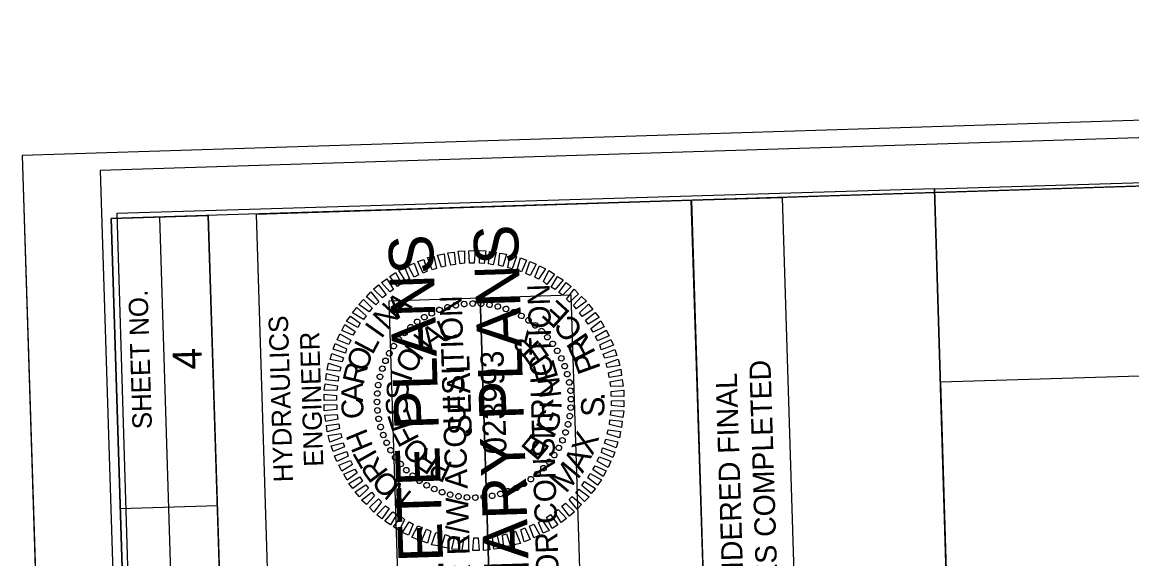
# Model space of a CAD drawing. Extents: x 2326025 to 2327173, y 123144 to 125024.
# Drawn here: x 2326025.5 to 2326312.3, y 124884.9 to 125023.6 of the extents above; entities that cross this region are included whole.
import ezdxf

# ---------------------------------------------------------------- set-up
doc = ezdxf.new("R2010")
doc.units = 0
for name, color, linetype in [('Sheet Clip Boundary CELL', 7, 'Continuous'), ('Sheet Cutting Line CELL', 7, 'Continuous'), ('Sheet Data Field CELL', 7, 'Continuous'), ('Sheet Layout Plan Border', 7, 'Continuous'), ('Sheet PE Seal Cell', 7, 'Continuous'), ('Sheet Plan CELL', 7, 'Continuous'), ('Sheet Plan Layout CELL', 7, 'Continuous'), ('Sheet Plot Border Inside CELL', 7, 'Continuous'), ('Sheet Plot Border Outside CELL', 7, 'Continuous'), ('Sheet Sticker Exception Certification CELL', 7, 'Continuous'), ('Sheet Sticker Incomplete CELL', 7, 'Continuous'), ('Sheet Sticker Preliminary CELL', 7, 'Continuous'), ('Typical Detail Wedge2 CELL', 7, 'Continuous')]:
    doc.layers.add(name, color=color, linetype=linetype)

msp = doc.modelspace()

# ---------------------------------------------------------------- linework, layer by layer
at = {"layer": 'Sheet Clip Boundary CELL'}
msp.add_lwpolyline([(2327143.22, 123556.44), (2327101.01, 124955.82), (2326262.87, 124930.53), (2326268.58, 124741.36), (2326057.19, 124734.98), (2326093.7, 123524.78)], close=True, dxfattribs=at)
at = {"layer": 'Sheet Cutting Line CELL'}
msp.add_line((2326025.47, 124989.14), (2326078.49, 123306.48), dxfattribs=at)
at = {"layer": 'Sheet Layout Plan Border'}
msp.add_lwpolyline([(2327143.22, 123556.44), (2327101.01, 124955.82), (2326262.87, 124930.53), (2326268.58, 124741.36), (2326057.19, 124734.98), (2326093.7, 123524.78)], close=True, dxfattribs=at)
at = {"layer": 'Sheet PE Seal Cell'}
for p, q in [((2326133.33, 124949.29), (2326133.33, 124949.29)), ((2326135.41, 124949.95), (2326135.41, 124949.95)), ((2326137.6, 124950.42), (2326137.6, 124950.42)), ((2326139.73, 124950.79), (2326139.73, 124950.79)), ((2326141.93, 124950.91), (2326141.93, 124950.91)), ((2326144.14, 124950.83), (2326144.14, 124950.83)), ((2326146.3, 124950.54), (2326146.3, 124950.54)), ((2326148.41, 124950.16), (2326148.41, 124950.16)), ((2326150.53, 124949.53), (2326150.53, 124949.53)), ((2326127.57, 124946.15), (2326127.57, 124946.15)), ((2326129.44, 124947.36), (2326129.44, 124947.36)), ((2326131.36, 124948.42), (2326131.36, 124948.42)), ((2326152.56, 124948.69), (2326152.56, 124948.69)), ((2326154.54, 124947.75), (2326154.54, 124947.75)), ((2326156.38, 124946.56), (2326156.38, 124946.56)), ((2326124.26, 124943.3), (2326124.26, 124943.3)), ((2326125.86, 124944.85), (2326125.86, 124944.85)), ((2326158.17, 124945.27), (2326158.17, 124945.27)), ((2326159.76, 124943.82), (2326159.76, 124943.82)), ((2326122.81, 124941.7), (2326122.81, 124941.7)), ((2326161.32, 124942.21), (2326161.32, 124942.21)), ((2326162.62, 124940.5), (2326162.62, 124940.5)), ((2326120.33, 124938.07), (2326120.33, 124938.07)), ((2326121.52, 124939.91), (2326121.52, 124939.91)), ((2326163.83, 124938.64), (2326163.83, 124938.64)), ((2326119.39, 124936.09), (2326119.39, 124936.09)), ((2326164.89, 124936.72), (2326164.89, 124936.72)), ((2326165.75, 124934.75), (2326165.75, 124934.75)), ((2326117.92, 124931.94), (2326117.92, 124931.94)), ((2326118.55, 124934.06), (2326118.55, 124934.06)), ((2326166.42, 124932.67), (2326166.42, 124932.67)), ((2326117.53, 124929.83), (2326117.53, 124929.83)), ((2326166.89, 124930.48), (2326166.89, 124930.48)), ((2326117.25, 124927.67), (2326117.25, 124927.67)), ((2326142.27, 124925.81), (2326142.27, 124925.81)), ((2326167.26, 124928.34), (2326167.26, 124928.34)), ((2326167.37, 124926.15), (2326167.37, 124926.15)), ((2326117.17, 124925.46), (2326117.17, 124925.46)), ((2326117.29, 124923.27), (2326117.29, 124923.27)), ((2326167.29, 124923.94), (2326167.29, 124923.94)), ((2326117.66, 124921.13), (2326117.66, 124921.13)), ((2326167.01, 124921.78), (2326167.01, 124921.78)), ((2326118.13, 124918.94), (2326118.13, 124918.94)), ((2326165.99, 124917.55), (2326165.99, 124917.55)), ((2326166.63, 124919.67), (2326166.63, 124919.67)), ((2326118.79, 124916.86), (2326118.79, 124916.86)), ((2326119.66, 124914.89), (2326119.66, 124914.89)), ((2326165.16, 124915.52), (2326165.16, 124915.52)), ((2326120.72, 124912.97), (2326120.72, 124912.97)), ((2326163.03, 124911.7), (2326163.03, 124911.7)), ((2326164.22, 124913.54), (2326164.22, 124913.54)), ((2326121.93, 124911.11), (2326121.93, 124911.11)), ((2326123.23, 124909.4), (2326123.23, 124909.4)), ((2326161.73, 124909.91), (2326161.73, 124909.91)), ((2326124.78, 124907.8), (2326124.78, 124907.8)), ((2326126.38, 124906.35), (2326126.38, 124906.35)), ((2326158.68, 124906.76), (2326158.68, 124906.76)), ((2326160.28, 124908.31), (2326160.28, 124908.31)), ((2326128.17, 124905.05), (2326128.17, 124905.05)), ((2326130.01, 124903.86), (2326130.01, 124903.86)), ((2326131.99, 124902.92), (2326131.99, 124902.92)), ((2326153.19, 124903.19), (2326153.19, 124903.19)), ((2326155.11, 124904.25), (2326155.11, 124904.25)), ((2326156.97, 124905.46), (2326156.97, 124905.46)), ((2326134.02, 124902.08), (2326134.02, 124902.08)), ((2326136.14, 124901.45), (2326136.14, 124901.45)), ((2326138.25, 124901.07), (2326138.25, 124901.07)), ((2326140.41, 124900.78), (2326140.41, 124900.78)), ((2326142.61, 124900.7), (2326142.61, 124900.7)), ((2326144.81, 124900.82), (2326144.81, 124900.82)), ((2326146.95, 124901.19), (2326146.95, 124901.19)), ((2326149.14, 124901.66), (2326149.14, 124901.66)), ((2326151.22, 124902.33), (2326151.22, 124902.33))]:
    msp.add_line(p, q, dxfattribs=at)
for points in [[(2326131.5, 124959.58), (2326130.25, 124962.75), (2326131.89, 124963.1), (2326132.54, 124959.97)], [(2326133.88, 124960.26), (2326132.83, 124963.38), (2326134.52, 124963.73), (2326134.92, 124960.59)], [(2326136.27, 124960.78), (2326135.47, 124964.01), (2326137.16, 124964.21), (2326137.46, 124961.02)], [(2326138.66, 124961.16), (2326138.16, 124964.4), (2326139.85, 124964.55), (2326139.85, 124961.3)], [(2326141.15, 124961.29), (2326140.9, 124964.53), (2326142.6, 124964.59), (2326142.35, 124961.33)], [(2326143.66, 124961.32), (2326143.65, 124964.57), (2326145.3, 124964.52), (2326144.86, 124961.25)], [(2326146.06, 124961.14), (2326146.26, 124964.35), (2326147.97, 124964.2), (2326147.27, 124960.93)], [(2326148.62, 124960.82), (2326148.93, 124963.93), (2326150.64, 124963.64), (2326149.69, 124960.46)], [(2326151.04, 124960.25), (2326151.59, 124963.37), (2326153.25, 124963.07), (2326152.1, 124959.88)], [(2326126.81, 124957.73), (2326125.22, 124960.64), (2326126.8, 124961.34), (2326127.89, 124958.27)], [(2326129.13, 124958.71), (2326127.73, 124961.72), (2326129.27, 124962.31), (2326130.16, 124959.24)], [(2326153.46, 124959.57), (2326154.27, 124962.7), (2326155.84, 124962.1), (2326154.53, 124959.06)], [(2326155.7, 124958.64), (2326156.75, 124961.78), (2326158.32, 124961.08), (2326156.81, 124958.18)], [(2326158.03, 124957.72), (2326159.19, 124960.61), (2326160.76, 124959.9), (2326158.99, 124957.15)], [(2326120.53, 124953.93), (2326118.35, 124956.32), (2326119.77, 124957.31), (2326121.46, 124954.56)], [(2326122.53, 124955.3), (2326120.55, 124957.89), (2326122.02, 124958.88), (2326123.51, 124956.03)], [(2326124.69, 124956.67), (2326122.85, 124959.41), (2326124.38, 124960.11), (2326125.62, 124957.3)], [(2326160.21, 124956.59), (2326161.62, 124959.43), (2326163.05, 124958.48), (2326161.14, 124955.81)], [(2326162.26, 124955.15), (2326163.87, 124957.9), (2326165.35, 124957), (2326163.23, 124954.53)], [(2326118.62, 124952.37), (2326116.3, 124954.6), (2326117.62, 124955.69), (2326119.6, 124953.11)], [(2326164.2, 124953.71), (2326166.07, 124956.37), (2326167.41, 124955.31), (2326165.13, 124953.04)], [(2326166.16, 124952.02), (2326168.13, 124954.63), (2326169.32, 124953.42), (2326166.98, 124951.25)], [(2326115.19, 124948.71), (2326112.52, 124950.68), (2326113.69, 124951.92), (2326115.91, 124949.69)], [(2326116.88, 124950.57), (2326114.46, 124952.64), (2326115.63, 124953.88), (2326117.66, 124951.34)], [(2326167.96, 124950.43), (2326170.09, 124952.69), (2326171.33, 124951.53), (2326168.69, 124949.5)], [(2326113.7, 124946.77), (2326110.89, 124948.53), (2326111.95, 124949.86), (2326114.37, 124947.74)], [(2326169.57, 124948.48), (2326171.9, 124950.7), (2326173, 124949.38), (2326170.25, 124947.55)], [(2326112.26, 124944.67), (2326109.31, 124946.33), (2326110.32, 124947.66), (2326112.83, 124945.79)], [(2326171.13, 124946.62), (2326173.62, 124948.55), (2326174.61, 124947.28), (2326171.77, 124945.54)], [(2326172.45, 124944.47), (2326175.09, 124946.4), (2326175.94, 124944.88), (2326173.08, 124943.53)], [(2326109.9, 124940.34), (2326106.91, 124941.5), (2326107.56, 124943.07), (2326110.41, 124941.46)], [(2326110.98, 124942.68), (2326108.08, 124943.94), (2326108.89, 124945.46), (2326111.55, 124943.65)], [(2326173.72, 124942.35), (2326176.47, 124944.04), (2326177.21, 124942.51), (2326174.2, 124941.27)], [(2326109.02, 124938.06), (2326105.84, 124939.11), (2326106.39, 124940.53), (2326109.33, 124939.22)], [(2326174.84, 124940.19), (2326177.69, 124941.58), (2326178.34, 124940.1), (2326175.18, 124938.95)], [(2326108.19, 124935.79), (2326105.07, 124936.44), (2326105.52, 124938), (2326108.51, 124936.85)], [(2326175.71, 124937.76), (2326178.68, 124939.01), (2326179.17, 124937.47), (2326176.1, 124936.73)], [(2326107.62, 124933.37), (2326104.35, 124933.77), (2326104.7, 124935.48), (2326107.83, 124934.43)], [(2326176.44, 124935.39), (2326179.55, 124936.54), (2326179.96, 124934.85), (2326176.72, 124934.34)], [(2326107.15, 124930.8), (2326103.94, 124931.15), (2326104.13, 124932.81), (2326107.26, 124932.01)], [(2326177.06, 124933), (2326180.24, 124933.91), (2326180.44, 124932.26), (2326177.25, 124931.81)], [(2326106.82, 124928.39), (2326103.57, 124928.49), (2326103.82, 124930.15), (2326106.99, 124929.6)], [(2326177.44, 124930.62), (2326180.62, 124931.27), (2326180.87, 124929.57), (2326177.63, 124929.42)], [(2326106.75, 124925.89), (2326103.5, 124925.78), (2326103.5, 124927.44), (2326106.76, 124927.09)], [(2326177.77, 124928.12), (2326181.01, 124928.48), (2326181.01, 124926.83), (2326177.76, 124926.92)], [(2326177.79, 124925.72), (2326181.04, 124925.83), (2326181.04, 124924.18), (2326177.78, 124924.52)], [(2326106.78, 124923.49), (2326103.54, 124923.13), (2326103.54, 124924.79), (2326106.79, 124924.69)], [(2326177.72, 124923.22), (2326180.98, 124923.12), (2326180.73, 124921.46), (2326177.56, 124922.02)], [(2326107.11, 124921), (2326103.93, 124920.35), (2326103.67, 124922.04), (2326106.92, 124922.19)], [(2326177.4, 124920.81), (2326180.61, 124920.46), (2326180.41, 124918.8), (2326177.29, 124919.61)], [(2326107.48, 124918.61), (2326104.31, 124917.71), (2326104.11, 124919.35), (2326107.29, 124919.8)], [(2326108.11, 124916.22), (2326104.99, 124915.08), (2326104.59, 124916.76), (2326107.82, 124917.27)], [(2326176.93, 124918.24), (2326180.19, 124917.85), (2326179.85, 124916.13), (2326176.71, 124917.19)], [(2326108.83, 124913.85), (2326105.87, 124912.6), (2326105.37, 124914.14), (2326108.45, 124914.88)], [(2326176.35, 124915.82), (2326179.48, 124915.17), (2326179.03, 124913.61), (2326176.04, 124914.76)], [(2326109.71, 124911.42), (2326106.85, 124910.03), (2326106.21, 124911.51), (2326109.37, 124912.66)], [(2326175.53, 124913.55), (2326178.71, 124912.5), (2326178.15, 124911.08), (2326175.21, 124912.39)], [(2326110.83, 124909.26), (2326108.08, 124907.57), (2326107.33, 124909.1), (2326110.34, 124910.34)], [(2326173.57, 124908.93), (2326176.46, 124907.67), (2326175.66, 124906.15), (2326173, 124907.96)], [(2326174.65, 124911.27), (2326177.63, 124910.11), (2326176.98, 124908.54), (2326174.13, 124910.15)], [(2326112.1, 124907.15), (2326109.46, 124905.21), (2326108.61, 124906.74), (2326111.47, 124908.08)], [(2326113.41, 124904.99), (2326110.92, 124903.06), (2326109.93, 124904.33), (2326112.78, 124906.07)], [(2326172.28, 124906.94), (2326175.24, 124905.28), (2326174.23, 124903.95), (2326171.72, 124905.82)], [(2326114.97, 124903.13), (2326112.64, 124900.91), (2326111.55, 124902.23), (2326114.29, 124904.06)], [(2326169.36, 124902.9), (2326172.02, 124900.93), (2326170.86, 124899.69), (2326168.64, 124901.92)], [(2326170.85, 124904.85), (2326173.65, 124903.08), (2326172.6, 124901.75), (2326170.18, 124903.87)], [(2326116.59, 124901.18), (2326114.46, 124898.92), (2326113.22, 124900.08), (2326115.86, 124902.11)], [(2326118.39, 124899.59), (2326116.42, 124896.98), (2326115.23, 124898.19), (2326117.56, 124900.36)], [(2326167.67, 124901.04), (2326170.08, 124898.97), (2326168.92, 124897.73), (2326166.89, 124900.27)], [(2326120.34, 124897.9), (2326118.47, 124895.24), (2326117.14, 124896.3), (2326119.42, 124898.57)], [(2326122.29, 124896.46), (2326120.67, 124893.71), (2326119.19, 124894.61), (2326121.32, 124897.08)], [(2326164.02, 124897.68), (2326166.2, 124895.29), (2326164.78, 124894.3), (2326163.09, 124897.05)], [(2326165.92, 124899.24), (2326168.24, 124897.01), (2326166.93, 124895.92), (2326164.94, 124898.51)], [(2326124.33, 124895.03), (2326122.92, 124892.18), (2326121.49, 124893.13), (2326123.41, 124895.8)], [(2326126.52, 124893.89), (2326125.36, 124891.01), (2326123.79, 124891.71), (2326125.55, 124894.46)], [(2326159.85, 124894.94), (2326161.69, 124892.2), (2326160.16, 124891.5), (2326158.92, 124894.31)], [(2326162.01, 124896.31), (2326163.99, 124893.72), (2326162.52, 124892.73), (2326161.03, 124895.58)], [(2326128.85, 124892.97), (2326127.8, 124889.83), (2326126.23, 124890.53), (2326127.74, 124893.43)], [(2326131.08, 124892.04), (2326130.28, 124888.91), (2326128.71, 124889.51), (2326130.01, 124892.55)], [(2326133.5, 124891.36), (2326132.95, 124888.24), (2326131.29, 124888.54), (2326132.44, 124891.73)], [(2326150.66, 124891.35), (2326151.71, 124888.23), (2326150.02, 124887.88), (2326149.62, 124891.02)], [(2326153.04, 124892.03), (2326154.29, 124888.87), (2326152.65, 124888.51), (2326152, 124891.65)], [(2326155.42, 124892.9), (2326156.81, 124889.9), (2326155.28, 124889.3), (2326154.38, 124892.37)], [(2326157.74, 124893.88), (2326159.33, 124890.98), (2326157.75, 124890.28), (2326156.65, 124893.34)], [(2326135.92, 124890.79), (2326135.62, 124887.68), (2326133.91, 124887.97), (2326134.86, 124891.15)], [(2326138.48, 124890.47), (2326138.28, 124887.26), (2326136.58, 124887.41), (2326137.28, 124890.68)], [(2326140.89, 124890.29), (2326140.89, 124887.04), (2326139.24, 124887.09), (2326139.69, 124890.36)], [(2326143.39, 124890.32), (2326143.64, 124887.08), (2326141.94, 124887.03), (2326142.19, 124890.29)], [(2326145.89, 124890.45), (2326146.39, 124887.22), (2326144.69, 124887.06), (2326144.69, 124890.31)], [(2326148.28, 124890.83), (2326149.08, 124887.6), (2326147.38, 124887.4), (2326147.08, 124890.59)]]:
    msp.add_lwpolyline(points, close=True, dxfattribs=at)
for centre, major_axis in [((2326141.92, 124950.88), (-0.01, 0.72)), ((2326131.36, 124948.38), (-0.313, 0.648)), ((2326133.36, 124949.25), (-0.256, 0.673)), ((2326135.44, 124949.94), (-0.196, 0.693)), ((2326137.57, 124950.44), (-0.135, 0.707)), ((2326139.74, 124950.76), (-0.073, 0.716)), ((2326144.11, 124950.82), (0.053, 0.718)), ((2326146.28, 124950.56), (0.115, 0.711)), ((2326148.42, 124950.12), (0.177, 0.698)), ((2326150.52, 124949.49), (0.237, 0.68)), ((2326152.55, 124948.68), (0.295, 0.657)), ((2326127.6, 124946.15), (-0.421, 0.584)), ((2326129.43, 124947.35), (-0.369, 0.618)), ((2326154.51, 124947.7), (0.351, 0.629)), ((2326156.37, 124946.55), (0.405, 0.596)), ((2326158.12, 124945.24), (0.455, 0.558)), ((2326124.29, 124943.29), (-0.516, 0.502)), ((2326125.88, 124944.79), (-0.471, 0.545)), ((2326159.76, 124943.79), (0.502, 0.516)), ((2326161.26, 124942.19), (0.545, 0.471)), ((2326121.53, 124939.9), (-0.596, 0.405)), ((2326122.84, 124941.66), (-0.558, 0.455)), ((2326162.61, 124940.48), (0.584, 0.421)), ((2326120.38, 124938.04), (-0.629, 0.351)), ((2326163.81, 124938.65), (0.618, 0.369)), ((2326164.85, 124936.72), (0.648, 0.313)), ((2326118.59, 124934.05), (-0.68, 0.237)), ((2326119.4, 124936.08), (-0.657, 0.295)), ((2326165.72, 124934.71), (0.673, 0.256)), ((2326117.96, 124931.96), (-0.698, 0.177)), ((2326166.4, 124932.64), (0.693, 0.196)), ((2326117.52, 124929.81), (-0.711, 0.115)), ((2326166.91, 124930.51), (0.707, 0.135)), ((2326167.22, 124928.34), (0.716, 0.073)), ((2326117.2, 124925.45), (-0.72, -0.01)), ((2326117.26, 124927.64), (-0.718, 0.053)), ((2326167.35, 124926.16), (0.72, 0.01)), ((2326117.32, 124923.27), (-0.716, -0.073)), ((2326167.29, 124923.97), (0.718, -0.053)), ((2326117.64, 124921.1), (-0.707, -0.135)), ((2326166.59, 124919.66), (0.698, -0.177)), ((2326167.03, 124921.8), (0.711, -0.115)), ((2326118.14, 124918.97), (-0.693, -0.196)), ((2326118.83, 124916.9), (-0.673, -0.256)), ((2326165.96, 124917.56), (0.68, -0.237)), ((2326119.69, 124914.89), (-0.648, -0.313)), ((2326164.17, 124913.57), (0.629, -0.351)), ((2326165.15, 124915.53), (0.657, -0.295)), ((2326120.73, 124912.96), (-0.618, -0.369)), ((2326121.93, 124911.13), (-0.584, -0.421)), ((2326163.02, 124911.71), (0.596, -0.405)), ((2326123.29, 124909.42), (-0.545, -0.471)), ((2326124.79, 124907.82), (-0.502, -0.516)), ((2326160.25, 124908.32), (0.516, -0.502)), ((2326161.71, 124909.96), (0.558, -0.455)), ((2326126.42, 124906.37), (-0.455, -0.558)), ((2326128.18, 124905.06), (-0.405, -0.596)), ((2326156.95, 124905.47), (0.421, -0.584)), ((2326158.66, 124906.82), (0.471, -0.545)), ((2326130.04, 124903.91), (-0.351, -0.629)), ((2326131.99, 124902.93), (-0.295, -0.657)), ((2326134.03, 124902.12), (-0.237, -0.68)), ((2326151.18, 124902.36), (0.256, -0.673)), ((2326153.19, 124903.23), (0.313, -0.648)), ((2326155.12, 124904.26), (0.369, -0.618)), ((2326136.12, 124901.49), (-0.177, -0.698)), ((2326138.27, 124901.05), (-0.115, -0.711)), ((2326140.44, 124900.79), (-0.053, -0.718)), ((2326142.63, 124900.73), (0.01, -0.72)), ((2326144.81, 124900.85), (0.073, -0.716)), ((2326146.97, 124901.17), (0.135, -0.707)), ((2326149.1, 124901.67), (0.196, -0.693))]:
    msp.add_ellipse(centre, major_axis=major_axis, ratio=0.999708, dxfattribs=at)
at = {"layer": 'Sheet Plan CELL'}
for p, q in [((2326067.31, 124773.29), (2326061.02, 124973.24)), ((2326079.84, 124773.7), (2326073.52, 124973.64)), ((2326079.84, 124773.7), (2326073.52, 124973.64)), ((2326050.91, 124897.86), (2326075.89, 124898.7))]:
    msp.add_line(p, q, dxfattribs=at)
for points in [[(2326048.48, 124972.88), (2326095.72, 123473.59), (2327145.2, 123506.66), (2327097.96, 125005.93)], [(2327145.2, 123506.66), (2326095.75, 123473.57), (2326054.77, 124772.91), (2326204.76, 124777.65), (2326198.47, 124977.58), (2327097.96, 125005.93)], [(2326089.17, 124874.09), (2326086.01, 124974.03), (2326198.47, 124977.58), (2326201.63, 124877.63)], [(2326054.77, 124772.91), (2326048.48, 124972.88), (2326073.52, 124973.64), (2326079.84, 124773.7)]]:
    msp.add_lwpolyline(points, close=True, dxfattribs=at)
at = {"layer": 'Sheet Plan Layout CELL'}
for points in [[(2326095.24, 123474.78), (2327144.73, 123506.47), (2327099.5, 125005.78), (2326261.37, 124980.5), (2326268.58, 124741.36), (2326057.19, 124734.98)], [(2326268.58, 124741.36), (2326261.37, 124980.52), (2326049.97, 124974.17), (2326057.19, 124734.98)]]:
    msp.add_lwpolyline(points, close=True, dxfattribs=at)
at = {"layer": 'Sheet Plot Border Inside CELL'}
msp.add_lwpolyline([(2327152.55, 123353.33), (2327100.07, 125018.49), (2326045.6, 124985.27), (2326098.07, 123320.1)], close=True, dxfattribs=at)
at = {"layer": 'Sheet Plot Border Outside CELL'}
msp.add_lwpolyline([(2327172.95, 123340.96), (2327119.93, 125023.63), (2326025.47, 124989.14), (2326078.49, 123306.48)], close=True, dxfattribs=at)
at = {"layer": 'Sheet Sticker Exception Certification CELL'}
for p, q in [((2326204.76, 124777.65), (2326198.46, 124977.58)), ((2326198.47, 124977.58), (2326221.96, 124978.32)), ((2326221.94, 124978.32), (2326228.24, 124778.39))]:
    msp.add_line(p, q, dxfattribs=at)
at = {"layer": 'Sheet Sticker Incomplete CELL'}
msp.add_lwpolyline([(2326148.48, 124805.44), (2326124.99, 124804.7), (2326120.36, 124951.63), (2326143.85, 124952.37)], close=True, dxfattribs=at)
at = {"layer": 'Sheet Sticker Preliminary CELL'}
msp.add_lwpolyline([(2326171.97, 124806.18), (2326148.48, 124805.44), (2326143.85, 124952.37), (2326167.34, 124953.11)], close=True, dxfattribs=at)

# ---------------------------------------------------------------- texts
at = {"layer": 'Sheet Data Field CELL'}
msp.add_text('4', height=7.5, rotation=91.8048, dxfattribs=at).set_placement((2326071.97, 124933.91))
at = {"layer": 'Sheet PE Seal Cell'}
for s, height, rotation, p in [('A', 5.64, 40.4219, (2326122.65, 124946.8)), ('N', 5.64, 47.6237, (2326119.8, 124943.76)), ('I', 5.64, 54.8249, (2326118.31, 124941.56)), ('L', 5.64, 24.2056, (2326134.35, 124940.81)), ('N', 5.64, 52.2814, (2326128.45, 124935.83)), ('A', 5.64, 33.5651, (2326130.96, 124938.76)), ('R', 5.64, 134.2862, (2326159.57, 124940.46)), ('L', 5.64, 62.0257, (2326116.04, 124937.44)), ('E', 5.64, 124.9289, (2326162.03, 124936.98)), ('O', 5.64, 69.226, (2326114.33, 124932.98)), ('O', 5.64, 61.6383, (2326126.56, 124932.41)), ('023993', 5.998, 91.8048, (2326150.72, 124912.04)), ('R', 5.64, 76.4259, (2326113.69, 124929.61)), ('SEAL', 5.998, 91.8048, (2326141.7, 124916.98)), ('E', 5.64, 106.2166, (2326164.15, 124931.75)), ('I', 5.64, 70.9944, (2326125.92, 124930.39)), ('N', 5.64, 96.8612, (2326164.9, 124926.82)), ('A', 5.64, 90.8251, (2326113.62, 124925.4)), ('S', 5.64, 89.7052, (2326125.36, 124926.07)), ('C', 5.64, 98.0247, (2326114.05, 124921.46)), ('S', 5.64, 99.0604, (2326125.52, 124922.48)), ('E', 5.64, 108.4159, (2326126.68, 124919.06)), ('G', 5.64, 68.795, (2326163.16, 124916.86)), ('I', 5.64, 87.506, (2326164.86, 124923.47)), ('N', 5.64, 59.4387, (2326161.04, 124912.99)), ('H', 5.64, 112.4243, (2326116.28, 124913.93)), ('F', 5.64, 117.7718, (2326128.28, 124915.91)), ('O', 5.64, 136.486, (2326131.33, 124912.7)), ('E', 5.64, 50.0817, (2326158.43, 124909.91)), ('T', 5.64, 119.6246, (2326118.04, 124910.73)), ('R', 5.64, 126.8253, (2326120.34, 124907.41)), ('R', 5.64, 145.8444, (2326133.83, 124911.03)), ('P', 5.64, 155.2037, (2326137.08, 124909.53)), ('O', 5.64, 134.0265, (2326123.55, 124904.06)), ('N', 5.64, 141.2283, (2326126.52, 124901.85))]:
    msp.add_text(s, height=height, rotation=rotation, dxfattribs=at).set_placement(p)
at = {"layer": 'Sheet Plan CELL'}
for s, p in [('SHEET NO.', (2326059.02, 124918.48)), ('HYDRAULICS', (2326095.49, 124904.77)), ('ENGINEER', (2326103.33, 124908.78))]:
    msp.add_text(s, height=5, rotation=91.8048, dxfattribs=at).set_placement(p)
at = {"layer": 'Sheet Sticker Exception Certification CELL'}
for s, p in [('UNLESS ALL SIGNATURES COMPLETED', (2326223.39, 124794.24)), ('DOCUMENT NOT CONSIDERED FINAL', (2326214.43, 124799.03))]:
    msp.add_text(s, height=5.5, rotation=91.8048, dxfattribs=at).set_placement(p)
at = {"layer": 'Sheet Sticker Incomplete CELL'}
for s, height, p in [('INCOMPLETE PLANS', 11.52, (2326136.51, 124814.02)), ('DO NOT USE FOR R/W ACQUISITION', 5.76, (2326143.35, 124817.49))]:
    msp.add_text(s, height=height, rotation=91.8048, dxfattribs=at).set_placement(p)
at = {"layer": 'Sheet Sticker Preliminary CELL'}
for s, height, p in [('PRELIMINARY PLANS', 11.52, (2326158.62, 124812.26)), ('DO NOT USE FOR CONSTRUCTION', 5.76, (2326165.91, 124825.6))]:
    msp.add_text(s, height=height, rotation=91.8048, dxfattribs=at).set_placement(p)
at = {"layer": 'Typical Detail Wedge2 CELL'}
for s, rotation, p in [('E', 137.8431, (2326167.43, 124948.53)), ('C', 128.2694, (2326170.86, 124944.03)), ('I', 124.4709, (2326172, 124942.1)), ('R', 116.9973, (2326173.87, 124938.1)), ('P', 109.8943, (2326175.14, 124934.1)), ('S', 88.3537, (2326175.89, 124921.45)), ('.', 95.6728, (2326176.17, 124925.77)), ('X', 70.5344, (2326172.95, 124911.37)), ('A', 61.702, (2326170.36, 124906.83)), ('M', 50.1827, (2326166.01, 124901.6))]:
    msp.add_text(s, height=6, rotation=rotation, dxfattribs=at).set_placement(p)

doc.saveas('drawing.dxf')
